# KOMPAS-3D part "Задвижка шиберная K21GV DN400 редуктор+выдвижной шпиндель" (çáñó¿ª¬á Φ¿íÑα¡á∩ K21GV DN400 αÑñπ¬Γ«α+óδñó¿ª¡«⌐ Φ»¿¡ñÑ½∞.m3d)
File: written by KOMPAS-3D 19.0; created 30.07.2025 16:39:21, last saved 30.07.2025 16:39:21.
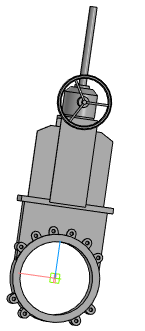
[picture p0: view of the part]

Document properties: Полное имя файла: Задвижка шиберная K21GV DN400 редуктор+выдвижной шпиндель.a3d

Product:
- Part/product: Задвижка шиберная K21GV DN400 редуктор+выдвижной шпиндель
    Масса: 166.23

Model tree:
1. Операция без истории:1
